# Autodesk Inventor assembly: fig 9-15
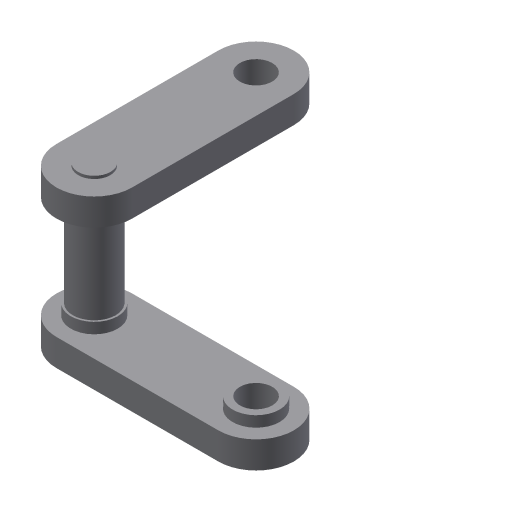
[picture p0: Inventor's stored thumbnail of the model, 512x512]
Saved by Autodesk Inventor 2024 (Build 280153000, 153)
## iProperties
Shininess: 64.0
Length Units: 11269
Angle Units: 11279
Time Units: 11290
Mass Units: 11283
Length Display Precision: 3
Angle Display Precision: 2
Created: 2002-01
Part Number: fig 9-15
Document SubType Name: Assembly
Designer: ***
Density: 0.0
Volumn: 0.0
Area: 0.0
PropertySet Name: Model Information
Control State: 0
Master: False
Checked Out: False
Author: ***
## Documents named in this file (3)
- D:\PROJECTS\Project 2023\RESOURCES INVENTOR 2024\RESOURCES INVENTOR 2024\Inventor_2023_Part\Inventor_2024_Part\c09_Inv_2024_prt\fig 9-15.iam
- D:\PROJECTS\Project 2023\RESOURCES INVENTOR 2024\RESOURCES INVENTOR 2024\Inventor_2023_Part\Inventor_2024_Part\c09_Inv_2024_prt\Part5.ipt
- D:\PROJECTS\Project 2023\RESOURCES INVENTOR 2024\RESOURCES INVENTOR 2024\Inventor_2023_Part\Inventor_2024_Part\c09_Inv_2024_prt\Part6.ipt
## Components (3 placed, 2 different names)
1. Part5:1 — Insert:1, Angle:1
2. Part6:1 — Insert:1, Insert:2
3. Part5:2 — Insert:2, Angle:1
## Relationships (3: Insert 2, Angle 1)
- Insert:1: Part5:1 ↔ Part6:1
- Insert:2: Part6:1 ↔ Part5:2
- Angle:1: Part5:1 ↔ Part5:2
